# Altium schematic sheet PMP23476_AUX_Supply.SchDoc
size 431 x 279 mm; Date: Not shown in title block; ApprovedBy: Not shown in title block; CheckedBy: Not shown in title block; Author: Not shown in title block; CompanyName: Not shown in title block; Engineer: Not shown in title block; Organization: Not shown in title block; Address1: Not shown in title block; Address2: Not shown in title block; Address3: Not shown in title block; Address4: Not shown in title block; DocumentNumber: 1; Revision: Use project parameter SCH_Rev; SheetNumber: 1; SheetTotal: 1; PageSetup: Record=PageOptions¦CenterHorizontal=True¦CenterVertical=True¦PrintScale=1.00¦XCorrection=1.00¦YCorrection=1.00¦PrintKind=0¦BorderSize=5000000¦LeftOffset=0¦BottomOffset=0¦Orientation=2¦PaperLength=1000¦PaperWidth=1000¦Scale=100¦PaperSource=15¦PrintQuality=600¦MediaType=1¦DitherType=10¦PaperKind=Letter¦PrintScaleMode=1
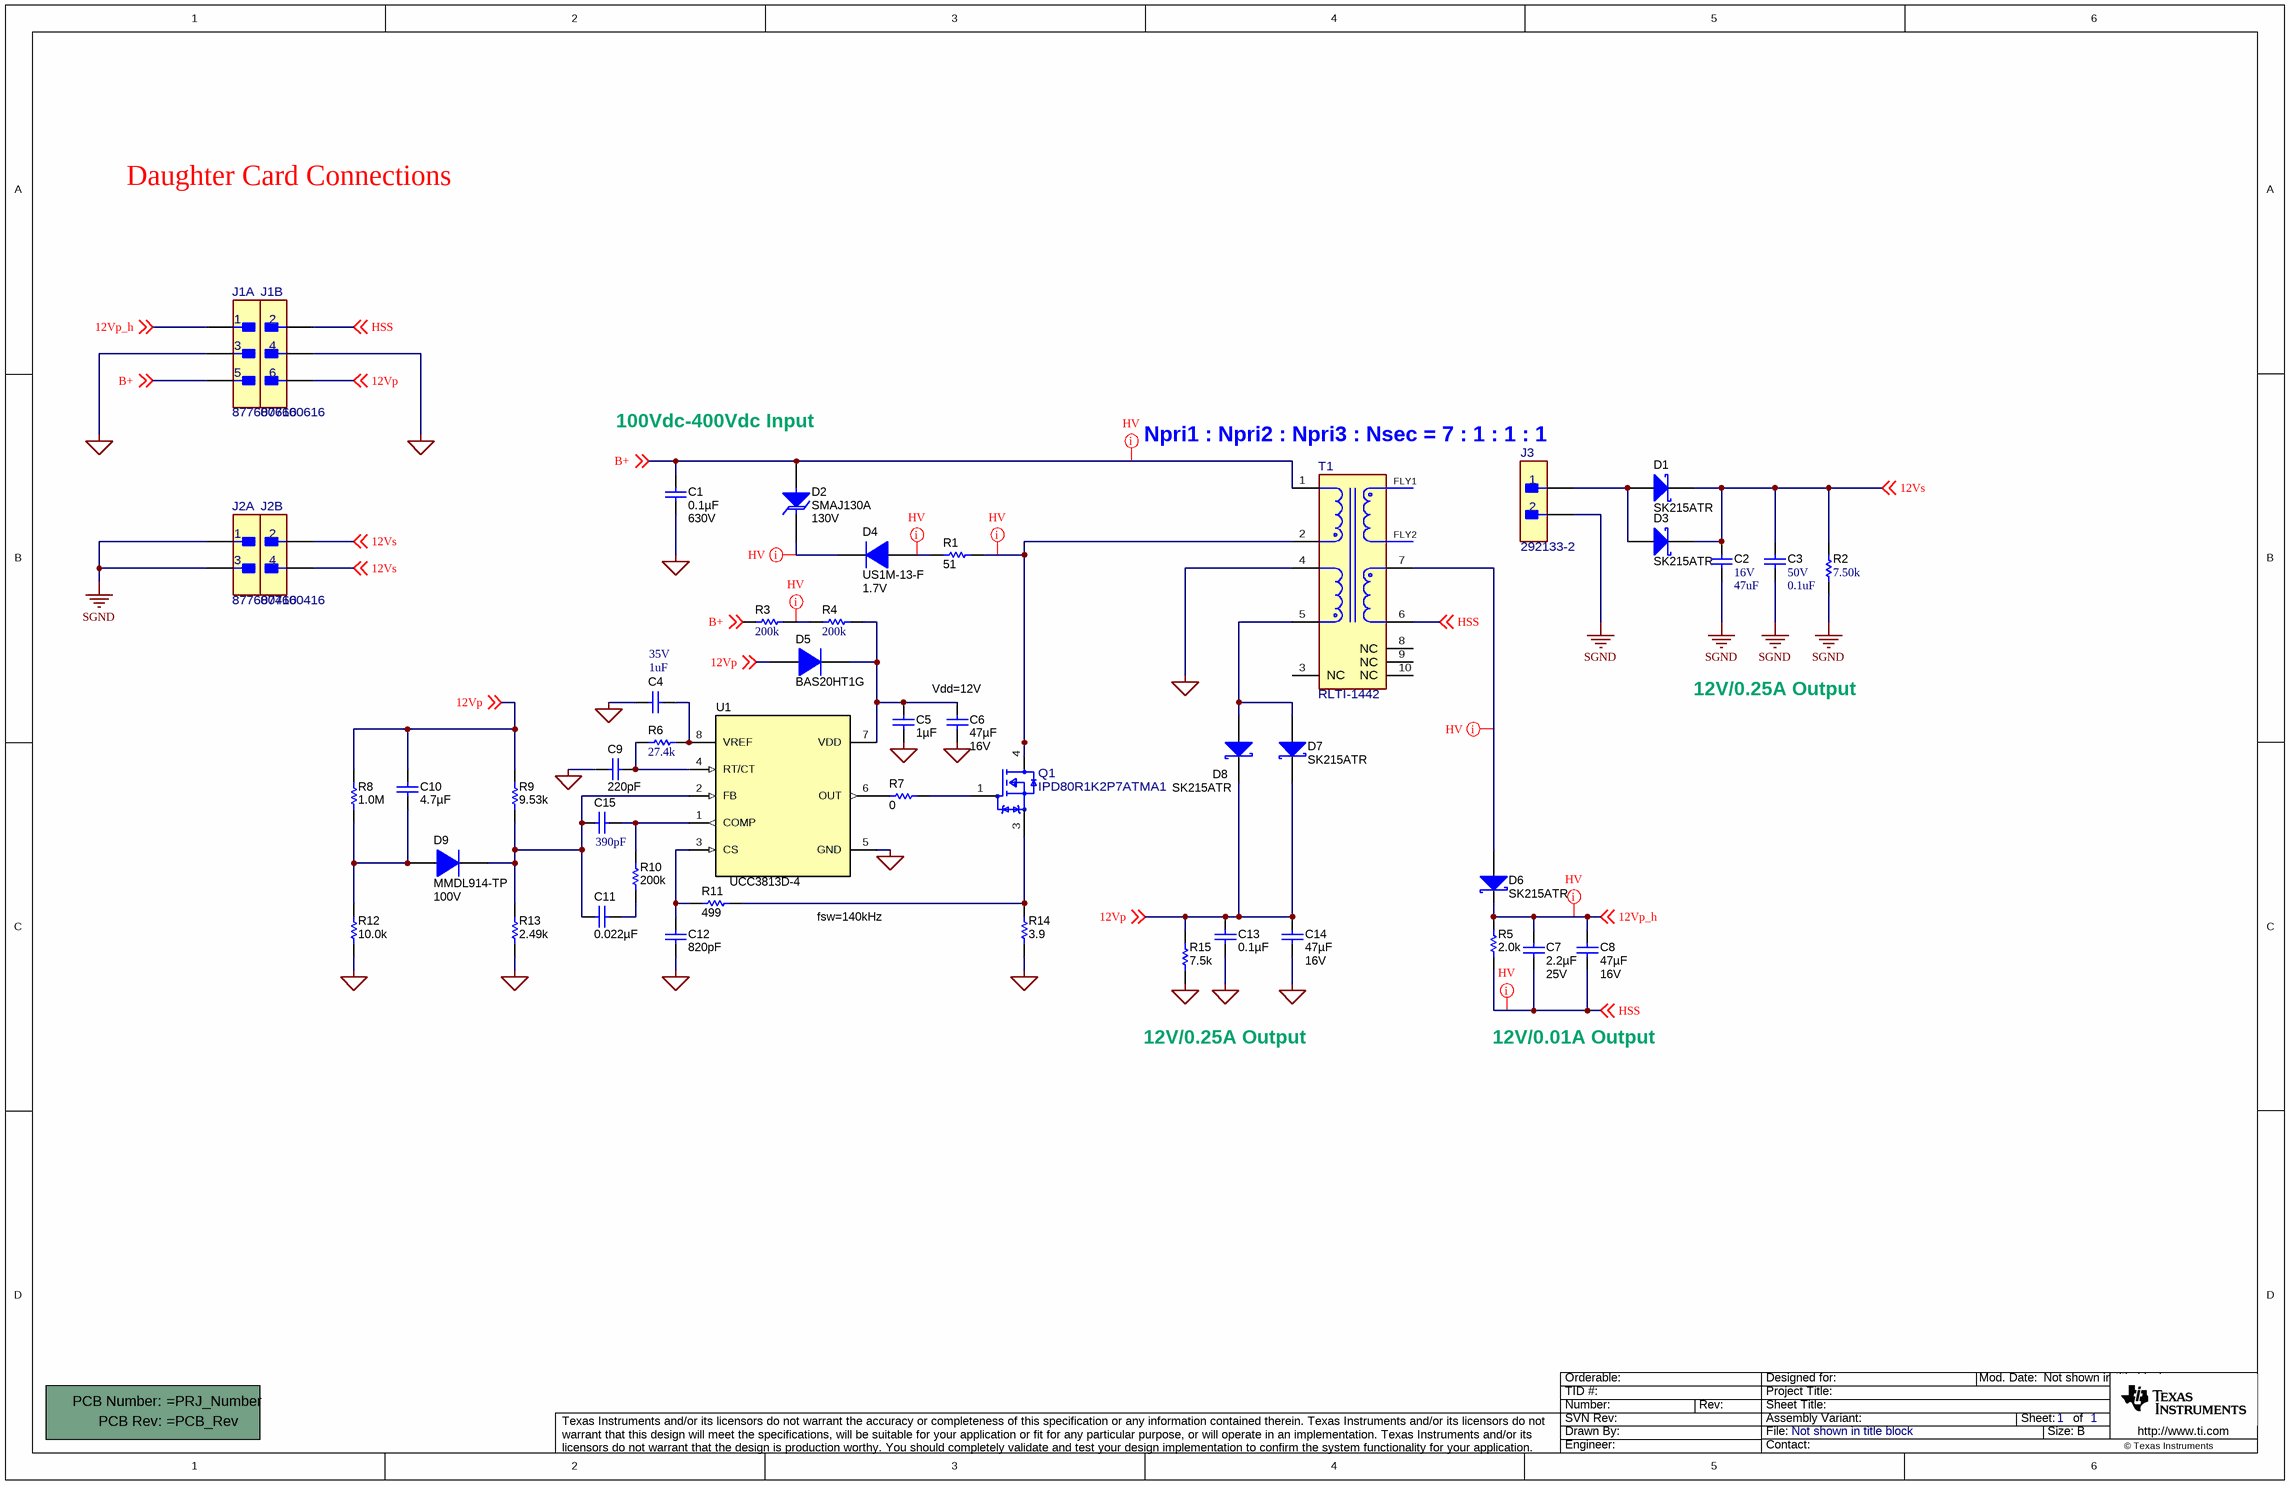
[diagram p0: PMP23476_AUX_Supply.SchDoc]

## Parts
!PCB1  Printed Circuit Board  (value not drawn)  (mechanical)
C1  ValueDisplayed: 0.1µF  Value2: 630V  [1812]  (hidden comment: GRM43DR72J104KW01L)
C2  VDC_V: 16V  ValueDisplayed: 47uF  [1210_270]  (hidden comment: GRM32EC81C476ME15L)
C3  VDC_V: 50V  ValueDisplayed: 0.1uF  [0402]  (hidden comment: GRM155R71H104ME14D)
C4  VDC_V: 35V  ValueDisplayed: 1uF  [0603]  (hidden comment: GMK107BJ105KA-T)
C5  ValueDisplayed: 1µF  [0805_HV]  (hidden comment: CL21B105KBFNNNE)
C6  ValueDisplayed: 47µF  Value2: 16V  [1210_270]  (hidden comment: GRM32ER61C476KE15L)
C7  ValueDisplayed: 2.2µF  Value2: 25V  [1206]  (hidden comment: 12063D225KAT2A)
C8  ValueDisplayed: 47µF  Value2: 16V  [1210_270]  (hidden comment: GRM32ER61C476KE15L)
C9  ValueDisplayed: 220pF  [0603]  (hidden comment: 06031C221KAT2A)
C10  ValueDisplayed: 4.7µF  [0805_HV]  (hidden comment: 0805ZD475KAT2A)
C11  ValueDisplayed: 0.022µF  [0402]  (hidden comment: GRM155R61C223KA01D)
C12  ValueDisplayed: 820pF  [0402]  (hidden comment: C0402C821J5GAC7867)
C13  ValueDisplayed: 0.1µF  [0402]  (hidden comment: 885012205037)
C14  ValueDisplayed: 47µF  Value2: 16V  [1210_270]  (hidden comment: GRM32ER61C476KE15L)
C15  ValueDisplayed: 390pF  [0402]  (hidden comment: GRM1555C1E391JA01D)
D1  SK215ATR  [SMA]
D2  SMAJ130A  value 130V  [SMA]
D3  SK215ATR  [SMA]
D4  US1M-13-F  value 1.7V  [SMA]
D5  BAS20HT1G  [sod-323]
D6  SK215ATR  [SMA]
D7  SK215ATR  [SMA]
D8  SK215ATR  [SMA]
D9  MMDL914-TP  value 100V  [sod-323]
J1  877600616  [FP-877600616_HDR6-MFG]  (parts A,B of 2)
J2  877600416  [FP-877600416_HDR4-MFG]  (parts A,B of 2)
J3  292133-2  [FP-292133-2_HDR2-MFG]
Q1  IPD80R1K2P7ATMA1  [FP-IPD80R1K2P7ATMA1_DPAK-MFG]
R1  ValueDisplayed: 51  [1206]  (hidden comment: CRCW120651R0JNEA)
R2  ValueDisplayed: 7.50k  [0402]  (hidden comment: CRCW04027K50FKED)
R3  ValueDisplayed: 200k  [1206]  (hidden comment: CRCW1206200KJNEA)
R4  ValueDisplayed: 200k  [1206]  (hidden comment: CRCW1206200KJNEA)
R5  ValueDisplayed: 2.0k  [1206]  (hidden comment: CRCW12062K00JNEA)
R6  ValueDisplayed: 27.4k  [0603]  (hidden comment: RC0603FR-0727K4L)
R7  ValueDisplayed: 0  [0603]  (hidden comment: CRCW06030000Z0EA)
R8  ValueDisplayed: 1.0M  [0402]  (hidden comment: CRCW04021M00JNED)
R9  ValueDisplayed: 9.53k  [0402]  (hidden comment: CRCW04029K53FKED)
R10  ValueDisplayed: 200k  [0402]  (hidden comment: CRCW0402200KFKED)
R11  ValueDisplayed: 499  [0402]  (hidden comment: CRCW0402499RFKED)
R12  ValueDisplayed: 10.0k  [0402]  (hidden comment: CRCW040210K0FKED)
R13  ValueDisplayed: 2.49k  [0402]  (hidden comment: CRCW04022K49FKED)
R14  ValueDisplayed: 3.9  [0603]  (hidden comment: RC0603FR-073R9L)
R15  ValueDisplayed: 7.5k  [0402]  (hidden comment: CRCW04027K50JNED)
T1  RLTI-1442  [FP-RLTI-1442_PTH_XFRMR_0_IN51_0IN56-MFG]
U1  UCC3813D-4  [D0008A_N]

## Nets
GND_PRI: C1.2 C4.2 C5.2 C6.1 C9.1 C12.2 C13.2 C14.1 J1.3 J1.4 R12.1 R13.1 R14.1 R15.1 T1.4(PGND1) U1.5(GND)
SGND: C2.2 C3.2 J2.1 J2.3 J3.2 R2.1
12Vp: C10.1 C13.1 C14.2 D5.2(A) D7.1(K) D8.1(K) J1.6 R8.2 R9.2 R15.2 ; off-sheet 12Vp
12Vp_h: C7.1 C8.2 D6.1(K) J1.1 R5.2 ; off-sheet 12Vp_h
12Vs: C2.1 C3.1 D1.1(K) D3.1(K) J2.2 J2.4 R2.2 ; off-sheet 12Vs
B+: C1.1 D2.2(A) J1.5 R3.1 T1.1(VDC+) ; off-sheet B+
HSS: C7.2 C8.1 J1.2 R5.1 T1.6(PGND2) ; off-sheet HSS
NetC4_1: C4.1 R6.2 U1.8(VREF)
NetC5_1: C5.1 C6.2 D5.1(K) R4.2 U1.7(VDD)
NetC9_2: C9.2 R6.1 U1.4(RT/CT)
NetC10_2: C10.2 D9.2(A) R8.1 R12.2
NetC11_1: C11.1 R10.1
NetC11_2: C11.2 C15.2 D9.1(K) R9.1 R13.2 U1.2(FB)
NetC12_1: C12.1 R11.1 U1.3(CS)
NetC15_1: C15.1 R10.2 U1.1(COMP)
NetD1_2: D1.2(A) D3.2(A) J3.1
NetD2_1: D2.1(K) D4.1(K)
NetD4_2: D4.2(A) R1.1
NetD6_2: D6.2(A) T1.7(VDD)
NetD7_2: D7.2(A) D8.2(A) T1.5(VCC)
NetQ1_1: Q1.1(Gate) R7.2
NetQ1_3: Q1.3(Source) R11.2 R14.2
NetQ1_4: Q1.4(Drain) R1.2 T1.2(VDRAIN)
NetR3_2: R3.2 R4.1
NetR7_1: R7.1 U1.6(OUT)

Not connected (* = marked no-connect by the designer): T1 3(NC) 8(NC) 9(NC) 10(NC)

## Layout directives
net class HV: 12Vp_h, B+, HSS, NetD2_1, NetD4_2, NetD6_2, NetQ1_4, NetR3_2

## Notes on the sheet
- Daughter Card Connections
- 100Vdc-400Vdc Input
- Npri1 : Npri2 : Npri3 : Nsec = 7 : 1 : 1 : 1
- (near C6) Vdd=12V
- 12V/0.25A Output
- fsw=140kHz
- 12V/0.01A Output

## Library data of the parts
!PCB1 = PCB: Manufacturer: Any; SymbolCreator: a0412235
C1 = GRM43DR72J104KW01L: CAP, CERM, 0.1uF, 630V, +/-10%, X7R, 1812; Manufacturer: MuRata; Polarized: N; CompType: Capacitor; U/M: EA; Cap_F: 0.0000001; Tolerance_%: 10; VDC_V: 630; TaMin_C: -55; TaMax_C: 125
C2 = CMP-0009201-2: CAP, CERM, 47 uF, 16 V, +/- 20%, X6S, 1210; Manufacturer: MuRata; TaMin_C: -55°C; Polarized: N; SizeAreaWB_mm2: 14.7; Value1: Unknown; U/M: EA; Value: 47uF; TaMax_C: 105°C; SizeZ_mm: 2.7; SizeX_mm: 3.2; SizeY_mm: 2.5; Cap_Case: 1210; SizeArea_mm2: 8; Cap_F: 47µF; AEC Category: Q200
C3 = CMP-0006675-2: CAP, CERM, 0.1 uF, 50 V, +/- 20%, X7R, 0402; Manufacturer: MuRata; TaMin_C: -55°C; Polarized: N; SizeAreaWB_mm2: 3; Value1: Unknown; U/M: EA; Value: 0.1uF; TaMax_C: 125°C; SizeZ_mm: 0.6; SizeX_mm: 1; SizeY_mm: 0.5; Cap_F: 100nF; AEC Category: Q200
C4 = CMP-0007150-5: CAP, CERM, 1 uF, 35 V, +/- 10%, X5R, 0603; Manufacturer: Taiyo Yuden; TaMin_C: -55°C; Polarized: N; SizeAreaWB_mm2: 4.68; Value1: Unknown; U/M: EA; Value: 1uF; TaMax_C: 85°C; SizeZ_mm: 1; SizeX_mm: 1.6; SizeY_mm: 0.8; SizeArea_mm2: 1.28; Cap_F: 1µF; AEC Category: Q200
C5 = CL21B105KBFNNNE: CAP, CERM, 1 µF, 50 V, +/- 10%, X7R, 0805; Manufacturer: Samsung Electro-Mechanics; Polarized: N; CompType: Capacitor; Value: 1uF; U/M: EA; Cap_F: 0.000001; Tolerance_%: 10; Value1: Unknown; VDC_V: 50; Value2: 50V; TaMin_C: -55; TaMax_C: 125; Cap_Case: 0805; AEC Category: Q200
C6 C8 C14 = GRM32ER61C476KE15L: CAP, CERM, 47 µF, 16 V, +/- 10%, X5R, 1210; Manufacturer: MuRata; Polarized: N; CompType: Capacitor; Value: 47uF; U/M: EA; Cap_F: 0.000047; Tolerance_%: 10; Value1: Unknown; VDC_V: 16; TaMin_C: -55; TaMax_C: 85; Cap_Case: 1210; SizeArea_mm2: 8; SizeAreaWB_mm2: 14.7; SizeX_mm: 3.2; SizeY_mm: 2.5; SizeZ_mm: 2.7; AEC Category: Q200
C7 = 12063D225KAT2A: CAP, CERM, 2.2 µF, 25 V, +/- 10%, X5R, 1206; Manufacturer: AVX; Polarized: N; CompType: Capacitor; Value: 2.2uF; U/M: EA; Cap_F: 0.0000022; Tolerance_%: 10; ESR_ohm: 0.016; Value1: 0.016 ohm; VDC_V: 25; TaMin_C: -55; TaMax_C: 85; AEC Category: Q200
C9 = 06031C221KAT2A: CAP, CERM, 220pF, 100V, +/-10%, X7R, 0603; Manufacturer: AVX; Polarized: N; CompType: Capacitor; U/M: EA; Cap_F: 0.00000000022; Tolerance_%: 10; ESR_Ohm: 0.579; Value1: 0.579 ohm; VDC_V: 100; TaMin_C: -55; TaMax_C: 125
C10 = 0805ZD475KAT2A: CAP, CERM, 4.7uF, 10V, +/-10%, X5R, 0805; Manufacturer: AVX; Polarized: N; CompType: Capacitor; U/M: EA; Cap_F: 0.0000047; Tolerance_%: 10; ESR_Ohm: 0.007; Value1: 0.007 ohm; TaMin_C: -55; TaMax_C: 85; Cap_Case: 0805
C11 = GRM155R61C223KA01D: CAP, CERM, 0.022 µF, 16 V, +/- 10%, X5R, 0402; Manufacturer: MuRata; Polarized: N; CompType: Capacitor; Value: 0.022uF; U/M: EA; Cap_F: 0.000000022; Tolerance_%: 10; Value1: Unknown; VDC_V: 16; Value2: 16V; TaMin_C: -55; TaMax_C: 85; SizeArea_mm2: 0.5; SizeAreaWB_mm2: 3; SizeX_mm: 1; SizeZ_mm: 0.6; AEC Category: Q200
C12 = GRM1555C1H681JA01D: CAP, CERM, 92- pF, 50 V, +/- 5%, C0G/NP0, 0402 *manually edited part*; Manufacturer: Kemet; Polarized: N; CompType: Capacitor; Value: 820pF; U/M: EA; Cap_F: 0.00000000068; Tolerance_%: 5; Value1: Unknown; VDC_V: 50; Value2: 50V; TaMin_C: -55; TaMax_C: 125; SizeArea_mm2: 0.5; SizeAreaWB_mm2: 3; SizeX_mm: 1; SizeZ_mm: 0.6; AEC Category: Q200
C13 = 885012205037: CAP, CERM, 0.1 µF, 16 V, +/- 10%, X7R, 0402; Manufacturer: Wurth Elektronik; Polarized: N; CompType: Capacitor; Value: 0.1uF; U/M: EA; Cap_F: 0.0000001; Tolerance_%: 10; Value1: Unknown; VDC_V: 16; Value2: 16V; TaMin_C: -55; TaMax_C: 125; SizeArea_mm2: 0.5; SizeAreaWB_mm2: 3; SizeX_mm: 1; SizeZ_mm: 0.6; AEC Category: Q200
C15 = CMP-0006381-2: CAP, CERM, 390 pF, 25 V, +/- 5%, C0G/NP0, 0402; Manufacturer: MuRata; TaMin_C: -55°C; Polarized: N; SizeAreaWB_mm2: 3; Value1: Unknown; U/M: EA; Value: 390pF; TaMax_C: 125°C; SizeZ_mm: 0.6; SizeX_mm: 1; SizeY_mm: 0.5; Value2: 25V; AEC Category: Q200
D1 D3 D6-D8 = CMP-0028966-2: Diode, Schottky, 150 V, 2 A, SMA; Manufacturer: SMC Diode Solutions; AEC Qualified: N; SizeZ_mm: 2.87; AEC Category: Q101; TJmax_C: 150°C; Value1: 2A; SizeY_mm: 2.92; Value2: 0.95V; Vr_V: 150V; SizeX_mm: 5.59; SizeAreaWB_mm2: 37.3428; SizeArea_mm2: 16.3228; Value: 150V; Vf_V: 950mV
D2 = SMAJ120A: DIODE TVS 130V 400W UNI 5% SMD; Manufacturer: Littelfuse; U/M: EA; Power_W: 400; Vr_V: 130; RJA_CperW: 120
D4 = US1M-13-F: Diode, Ultrafast, 1000V, 1A, SMA; Manufacturer: Diodes Inc.; U/M: EA; Vf_V: 1.7; Io_A: 1; Vr_V: 1000; TJmax_C: 150; RJC_CperW: 30
D5 = BAS316,115: DIODE SWITCH 200V 200MA SOD323; U/M: EA; Vf_V: 1.4; Value1: 0.25A; Vr_V: 100; Value2: 100V; TJmax_C: 150; Type: Ultrafast
D9 = MMDL914-TP: Diode, Switching, 100V, 0.2A, SOD-323; Manufacturer: Micro Commercial Components; U/M: EA; Vf_V: 1; Value2: 1V; Io_A: 0.2; Vr_V: 100; TJmax_C: 150; RJC_CperW: 635
J1 = CMP-0095636-1: Connector Header Through Hole, Right Angle 6 position 0.079" (2.00mm); Manufacturer: Molex; Voltage_V: 125V; SizeZ_mm: 4.3mm; DUT-Pitch_mm: 2mm; Row_Count: 2; Is Female: no; Current_A: 2A; Conn Gender: Male; ContactFinish: Gold,Nickel
J2 = CMP-0095635-1: Connector Header Through Hole, Right Angle 4 position 0.079" (2.00mm); Manufacturer: Molex; AEC Qualified: No; ContactFinish: Gold,Nickel; DUT-Pitch_mm: 2mm; Row_Count: 2; Conn Gender: Male; Voltage_V: 125V; SizeZ_mm: 4.3mm; Current_A: 2A
J3 = CMP-0095293-1: Connector Header Through Hole 2 position 0.079" (2.00mm); Manufacturer: TE Connectivity; Standoff Height: 0.2mm; ContactFinish: Tin; Conn Gender: Male; Current_A: 4A; DUT-Pitch_mm: 2mm; AEC Qualified: No; Conn Orientation: Vertical; Voltage_V: 125V; Row_Count: 1; SizeZ_mm: 7mm
Q1 = CMP-0098249-1: MOSFET N-Channel 800 V 4.5A (Tc) 37W (Tc) Surface Mount PG-TO252-3; Manufacturer: Infineon Technologies; SizeZ_mm: 2.48mm; TJmax_C: +150°C; Input Capacitace At Vds: 300pF @ 500V; Reverse Recovery Time: 580ns; Reverse Recovery Charge: 3800nC; Turn Off Delay Time: 40ns; Threshold Vgs Max: 3.5V; Number Of N Channels: 1; Typ Forward Diode Voltage: 0.9V; AEC Qualified: No; QgTyp_nC: 11nC @ 10V; Pulse Drain Current: 11A; Turn On Delay Time: 10ns; Threshold Vgs Min: 2.5V; ChMode: False; Vgs_V: 20V; Rthja Max: 62°C/W; VdsMax_V: 800V
R1 = CRCW120651R0JNEA: RES, 51, 5%, 0.25 W, 1206; Manufacturer: Vishay-Dale; CompType: Resistor; Value: 51; Value_Code: 51R0; Tolerance_%: 5; Power_W: 0.25; Value2: 0.25W; VDC_V: 200; TempCo: 200 ppm/C; EIA_Code: E24; U/M: EA; AEC Category: Q200
R2 = CMP-0026555-2: RES, 7.50 k, 1%, 0.063 W, AEC-Q200 Grade 0, 0402; Manufacturer: Vishay-Dale; Power_W: 63mW; TempCo: 100 ppm/C; Value_Code: 7k50; Value: 7.50k; EIA_Code: E96; Res_ohm: 7.5k; SizeX_mm: 1; SizeY_mm: 0.5; SizeZ_mm: 0.6; Value2: 0.063W; AEC Qualified: Y; VDC_V: 50V; AEC Category: Q200; AEC Grade: 0
R3 R4 = CMP-0018624-3: RES, 200 k, 5%, 0.25 W, AEC-Q200 Grade 0, 1206; Manufacturer: Vishay-Dale; Power_W: 250mW; TempCo: 200 ppm/C; Value: 200k; EIA_Code: E24; SizeX_mm: 3.2; SizeY_mm: 1.6; SizeZ_mm: 1.35; Value2: 0.25W; SizeArea_mm2: 5.12; AEC Qualified: Y; VDC_V: 200V; AEC Category: Q200; AEC Grade: 0
R5 = CRCW12062K00JNEA: RES, 2.0 k, 5%, 0.25 W, 1206; Manufacturer: Vishay-Dale; CompType: Resistor; Value: 2.0k; Res_ohm: 2000; Value_Code: 2k00; Tolerance_%: 5; Power_W: 0.25; Value2: 0.25W; VDC_V: 200; TempCo: 200 ppm/C; EIA_Code: E24; U/M: EA; AEC Category: Q200
R6 = CMP-0022965-5: RES, 27.4 k, 1%, 0.1 W, 0603; Manufacturer: Yageo; Power_W: 100mW; TempCo: 100 ppm/C; Value_Code: 27k4; Value: 27.4k; EIA_Code: E96; SizeX_mm: 1.6; SizeY_mm: 0.8; SizeZ_mm: 1; Value2: 0.1W; SizeArea_mm2: 1.28; AEC Qualified: N; VDC_V: 75V; AEC Category: Q200; SizeAreaWB_mm2: 4.68
R7 = CRCW06030000Z0EA: RES, 0, 5%, 0.1 W, 0603; Manufacturer: Vishay-Dale; CompType: Resistor; Value: 0; Value_Code: 0000; Tolerance_%: 5; Power_W: 0.1; Value2: 0.1W; VDC_V: 75; TempCo: 200 ppm/C; EIA_Code: E24; U/M: EA; AEC Category: Q200
R8 = CRCW04021M00JNED: RES, 1.0 M, 5%, 0.063 W, 0402; Manufacturer: Vishay-Dale; CompType: Resistor; Value: 1.0Meg; Res_ohm: 1000000; Value_Code: 1M00; Tolerance_%: 5; Power_W: 0.063; Value2: 0.063W; VDC_V: 50; TempCo: 200 ppm/C; EIA_Code: E24; U/M: EA; AEC Category: Q200
R9 = CRCW04029K53FKED: RES, 9.53 k, 1%, 0.063 W, 0402; Manufacturer: Vishay-Dale; CompType: Resistor; Value: 9.53k; Res_ohm: 9530; Value_Code: 9k53; Tolerance_%: 1; Power_W: 0.063; Value2: 0.063W; VDC_V: 50; TempCo: 100 ppm/C; EIA_Code: E96; U/M: EA; AEC Category: Q200
R10 = CRCW0402200KFKED: RES, 200 k, 1%, 0.063 W, 0402; Manufacturer: Vishay-Dale; CompType: Resistor; Value: 200k; Res_ohm: 200000; Tolerance_%: 1; Power_W: 0.063; Value2: 0.063W; VDC_V: 50; TempCo: 100 ppm/C; EIA_Code: E96; U/M: EA; AEC Category: Q200
R11 = CRCW0402499RFKED: RES, 499, 1%, 0.063 W, 0402; Manufacturer: Vishay-Dale; CompType: Resistor; Value: 499; Value_Code: 499R; Tolerance_%: 1; Power_W: 0.063; Value2: 0.063W; VDC_V: 50; TempCo: 100 ppm/C; EIA_Code: E96; U/M: EA; AEC Category: Q200
R12 = CRCW040210K0FKED: RES, 10.0 k, 1%, 0.063 W, 0402; Manufacturer: Vishay-Dale; CompType: Resistor; Value: 10.0k; Res_ohm: 10000; Value_Code: 10k0; Tolerance_%: 1; Power_W: 0.063; Value2: 0.063W; VDC_V: 50; TempCo: 100 ppm/C; EIA_Code: E96; U/M: EA; AEC Category: Q200
R13 = CRCW04022K49FKED: RES, 2.49 k, 1%, 0.063 W, 0402; Manufacturer: Vishay-Dale; CompType: Resistor; Value: 2.49k; Res_ohm: 2490; Value_Code: 2k49; Tolerance_%: 1; Power_W: 0.063; Value2: 0.063W; VDC_V: 50; TempCo: 100 ppm/C; EIA_Code: E96; U/M: EA; AEC Category: Q200
R14 = CRCW060310R0FKEA: RES, 3.9, 1%, 0.1 W, 0603 *manually edited*; Manufacturer: Yageo; CompType: Resistor; Value: 3.9; Res_ohm: 10; Value_Code: 10R0; Tolerance_%: 1; Power_W: 0.1; Value2: 0.1W; VDC_V: 75; TempCo: 100 ppm/C; EIA_Code: E96; U/M: EA; AEC Category: Q200
R15 = CRCW04027K50JNED: RES, 7.5 k, 5%, 0.063 W, 0402; Manufacturer: Vishay-Dale; CompType: Resistor; Value: 7.5k; Res_ohm: 7500; Value_Code: 7k50; Tolerance_%: 5; Power_W: 0.063; Value2: 0.063W; VDC_V: 50; TempCo: 200 ppm/C; EIA_Code: E24; U/M: EA; AEC Category: Q200
T1 = CMP-0095385-1: Flyback for PMP23126; Manufacturer: Renco Electronics; Ind_H: 1mH; AEC Qualified: No; SizeZ_mm: 0.6inch; Rsec1_ohm: 0.12; DCR_ohm: 1.2; Ns1toNp: 1:0.142; Voltage_Isolation_Vrms: 1500VDC
U1 = UCC28C42DR: IC REG CTRLR PWM CM 8SOIC; Manufacturer: Texas Instruments; SymbolCreator: a0411947; U/M: EA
